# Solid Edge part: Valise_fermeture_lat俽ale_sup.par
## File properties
Author: Bernard DUMAS
Template: Normal.par
Last saved by: FR026244
Revision: 29
Application: Solid Edge
Densité: 460.000 kg/m^3
Précision: 0.9900
Document Number: 07
Revision: a
Project Name: Slamson
Material: Bois, Frêne
Style de face: Jaune kaki
Style de remplissage: Liège
Style virtuel: Frêne verni
Coef. of Thermal Exp: 0.0
Thermal Conductivity: 0.0
Specific Heat: 0.0
Modulus of Elasticity: 0.0
Poission's Ratio: 0.0
Yield Stress: 0.0
Ultimate Stress: 0.0
Elongation: 0.0
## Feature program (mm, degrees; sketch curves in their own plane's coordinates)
sketch for "unnamed Protrusion 1" plane through (0, 0, 0) normal (0, -1, 0) x-axis (1, 0, 0)
extrude "unnamed Protrusion 1" add finite 5 along +normal
fillet "Congé_1" radius 2
sketch for "Ajout_matière_10" #1 plane through (0, -5, 0) normal (0, -1, 0) x-axis (1, 0, 0)
sketch for "Ajout_matière_10" #2 plane through (0, -5, 0) normal (0, -1, 0) x-axis (1, 0, 0)
extrude "Ajout_matière_10" add finite 3 along +normal
sketch for "unnamed Cutout 1" plane through (0, -5, 0) normal (0, -1, 0) x-axis (1, 0, 0)
extrude "unnamed Cutout 1" cut through along -normal
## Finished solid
Body 1: solid body, 21 faces, 46 edges, 28 vertices.
  Faces by surface: plane 15, cylinder 6
  Edges by curve: line 38, circle 4, ellipse 4
Bounding box of the edges (mm): 75.000 x 8.000 x 45.000, from (-37.5, -8, -22.5) to (37.5, 0, 22.5).
Cylindrical faces by radius (mm): R2 x4, R3.1684 x1, R12.5 x1
Planar faces by outward normal: +x 3, +y 1, +z 3, -x 3, -y 3, -z 2
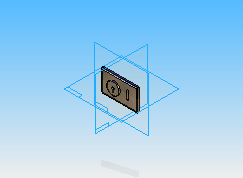
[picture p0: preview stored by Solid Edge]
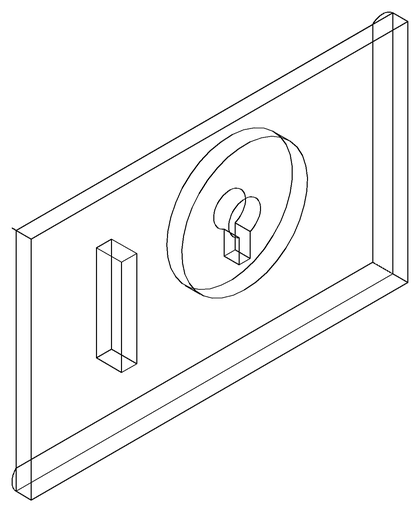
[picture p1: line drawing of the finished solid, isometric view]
